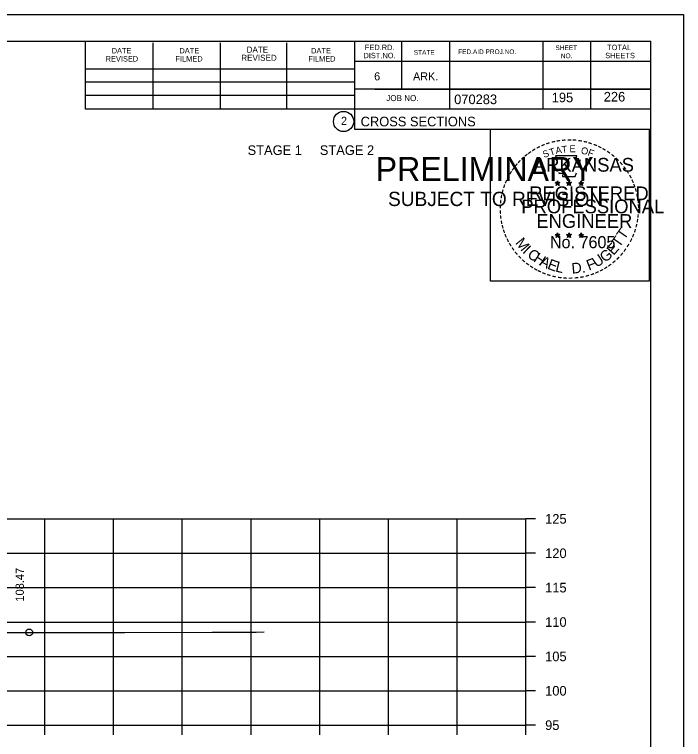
# Model space of a CAD drawing. Extents: x 1175611 to 1176402, y -433344 to -416213.
# Drawn here: x 1175846.5 to 1175943.9, y -422995.4 to -422890 of the extents above; entities that cross this region are included whole.
import ezdxf

# ---------------------------------------------------------------- set-up
doc = ezdxf.new("R2010")
doc.units = 0
for name, color, linetype in [('Default', 7, 'Continuous'), ('R_Axis', 7, 'Continuous'), ('R_Axis Annot', 7, 'Continuous'), ('R_Border', 7, 'Continuous'), ('R_Border Notes', 7, 'Continuous'), ('R_Border PE', 7, 'Continuous'), ('R_Border Prem', 7, 'Continuous'), ('R_Exist Surface', 7, 'Continuous'), ('R_Grid', 7, 'Continuous'), ('R_No Plot', 7, 'Continuous'), ('R_Xsect Elev', 7, 'Continuous')]:
    doc.layers.add(name, color=color, linetype=linetype)

msp = doc.modelspace()

# ---------------------------------------------------------------- linework, layer by layer
at = {"layer": 'R_Axis'}
for p, q in [((1175920.97, -422993.33), (1175920.97, -422963.33)), ((1175922.37, -422963.33), (1175920.97, -422963.33)), ((1175922.37, -422968.33), (1175920.97, -422968.33)), ((1175922.37, -422973.33), (1175920.97, -422973.33)), ((1175922.37, -422978.33), (1175920.97, -422978.33)), ((1175922.37, -422983.33), (1175920.97, -422983.33)), ((1175922.37, -422988.33), (1175920.97, -422988.33)), ((1175640.97, -422993.33), (1175920.97, -422993.33)), ((1175850.97, -422994.73), (1175850.97, -422993.33)), ((1175860.97, -422994.73), (1175860.97, -422993.33)), ((1175870.97, -422994.73), (1175870.97, -422993.33)), ((1175880.97, -422994.73), (1175880.97, -422993.33)), ((1175890.97, -422994.73), (1175890.97, -422993.33)), ((1175900.97, -422994.73), (1175900.97, -422993.33)), ((1175910.97, -422994.73), (1175910.97, -422993.33)), ((1175920.97, -422994.73), (1175920.97, -422993.33)), ((1175922.37, -422993.33), (1175920.97, -422993.33))]:
    msp.add_line(p, q, dxfattribs=at)
at = {"layer": 'R_Border'}
for p, q in [((1175622.97, -422893.87), (1175939.15, -422893.87)), ((1175856.89, -422903.75), (1175856.89, -422893.87)), ((1175866.75, -422903.75), (1175866.75, -422894.07)), ((1175876.51, -422903.75), (1175876.51, -422894.07)), ((1175886.19, -422903.75), (1175886.19, -422894.07)), ((1175896.05, -422893.87), (1175896.05, -422906.67)), ((1175902.89, -422893.87), (1175902.89, -422900.81)), ((1175909.83, -422893.87), (1175909.83, -422903.75)), ((1175923.41, -422893.87), (1175923.41, -422903.75)), ((1175930.35, -422893.87), (1175930.35, -422903.75)), ((1175939.15, -423099.33), (1175939.15, -422893.87)), ((1175939.15, -422896.81), (1175896.05, -422896.81)), ((1175939.15, -422896.79), (1175939.15, -422896.79)), ((1175856.89, -422897.89), (1175896.05, -422897.89)), ((1175856.89, -422899.75), (1175896.05, -422899.75)), ((1175939.15, -422900.81), (1175896.05, -422900.81)), ((1175899.01, -422900.81), (1175939.15, -422900.81)), ((1175856.89, -422903.75), (1175856.89, -422901.69)), ((1175856.89, -422901.69), (1175896.05, -422901.69)), ((1175939.15, -422903.75), (1175856.89, -422903.75)), ((1175896.05, -422906.67), (1175939.15, -422906.67))]:
    msp.add_line(p, q, dxfattribs=at)
msp.add_circle((1175894.44, -422905.53), 1.47, dxfattribs=at)
at = {"layer": 'R_Border PE'}
for p, q in [((1175925.23, -422914.42), (1175925.58, -422914.53)), ((1175925.23, -422914.42), (1175925.49, -422914.46)), ((1175925.23, -422914.42), (1175925.47, -422914.54)), ((1175925.37, -422914.83), (1175925.58, -422914.53)), ((1175925.37, -422914.83), (1175925.49, -422914.58)), ((1175925.37, -422914.83), (1175925.58, -422914.61)), ((1175925.58, -422914.17), (1175925.54, -422914.42)), ((1175925.58, -422914.53), (1175925.58, -422914.17)), ((1175925.58, -422914.17), (1175925.63, -422914.42)), ((1175925.93, -422914.42), (1175925.58, -422914.53)), ((1175925.8, -422914.83), (1175925.58, -422914.53)), ((1175925.8, -422914.83), (1175925.58, -422914.61)), ((1175925.93, -422914.42), (1175925.64, -422914.47)), ((1175925.8, -422914.83), (1175925.66, -422914.54)), ((1175925.93, -422914.42), (1175925.73, -422914.52)), ((1175926.9, -422914.42), (1175927.25, -422914.53)), ((1175926.9, -422914.42), (1175927.16, -422914.46)), ((1175926.9, -422914.42), (1175927.14, -422914.54)), ((1175927.04, -422914.83), (1175927.25, -422914.53)), ((1175927.04, -422914.83), (1175927.16, -422914.58)), ((1175927.04, -422914.83), (1175927.25, -422914.61)), ((1175927.25, -422914.17), (1175927.21, -422914.42)), ((1175927.25, -422914.53), (1175927.25, -422914.17)), ((1175927.25, -422914.17), (1175927.3, -422914.42)), ((1175927.6, -422914.42), (1175927.25, -422914.53)), ((1175927.47, -422914.83), (1175927.25, -422914.53)), ((1175927.47, -422914.83), (1175927.25, -422914.61)), ((1175927.6, -422914.42), (1175927.31, -422914.47)), ((1175927.47, -422914.83), (1175927.33, -422914.54)), ((1175927.6, -422914.42), (1175927.4, -422914.52)), ((1175928.67, -422914.43), (1175929.02, -422914.54)), ((1175928.67, -422914.43), (1175928.92, -422914.48)), ((1175928.67, -422914.43), (1175928.91, -422914.55)), ((1175928.8, -422914.84), (1175929.02, -422914.54)), ((1175928.8, -422914.84), (1175928.93, -422914.6)), ((1175928.8, -422914.84), (1175929.02, -422914.62)), ((1175929.02, -422914.18), (1175928.98, -422914.43)), ((1175929.02, -422914.54), (1175929.02, -422914.18)), ((1175929.02, -422914.18), (1175929.07, -422914.43)), ((1175929.36, -422914.43), (1175929.02, -422914.54)), ((1175929.23, -422914.84), (1175929.02, -422914.54)), ((1175929.23, -422914.84), (1175929.02, -422914.63)), ((1175929.36, -422914.43), (1175929.08, -422914.48)), ((1175929.23, -422914.84), (1175929.09, -422914.55)), ((1175929.36, -422914.43), (1175929.16, -422914.53)), ((1175925.23, -422921.99), (1175925.58, -422922.1)), ((1175925.23, -422921.99), (1175925.48, -422922.04)), ((1175925.23, -422921.99), (1175925.47, -422922.11)), ((1175925.58, -422921.74), (1175925.54, -422921.99)), ((1175925.58, -422922.1), (1175925.58, -422921.74)), ((1175925.58, -422921.74), (1175925.63, -422921.99)), ((1175925.93, -422921.99), (1175925.58, -422922.1)), ((1175925.93, -422921.99), (1175925.64, -422922.04)), ((1175925.93, -422921.99), (1175925.72, -422922.09)), ((1175926.9, -422921.99), (1175927.25, -422922.1)), ((1175926.9, -422921.99), (1175927.15, -422922.04)), ((1175926.9, -422921.99), (1175927.14, -422922.11)), ((1175927.25, -422921.74), (1175927.21, -422921.99)), ((1175927.25, -422922.1), (1175927.25, -422921.74)), ((1175927.25, -422921.74), (1175927.3, -422921.99)), ((1175927.6, -422921.99), (1175927.25, -422922.1)), ((1175927.6, -422921.99), (1175927.31, -422922.04)), ((1175927.6, -422921.99), (1175927.39, -422922.09)), ((1175928.67, -422922), (1175929.02, -422922.11)), ((1175928.67, -422922), (1175928.92, -422922.05)), ((1175928.67, -422922), (1175928.9, -422922.12)), ((1175929.02, -422921.75), (1175928.97, -422922)), ((1175929.02, -422922.11), (1175929.02, -422921.75)), ((1175929.02, -422921.75), (1175929.06, -422922)), ((1175929.36, -422922), (1175929.02, -422922.11)), ((1175929.36, -422922), (1175929.08, -422922.05)), ((1175929.36, -422922), (1175929.16, -422922.1)), ((1175925.36, -422922.4), (1175925.58, -422922.1)), ((1175925.36, -422922.4), (1175925.49, -422922.16)), ((1175925.36, -422922.4), (1175925.58, -422922.18)), ((1175925.79, -422922.4), (1175925.58, -422922.1)), ((1175925.79, -422922.4), (1175925.58, -422922.19)), ((1175925.79, -422922.4), (1175925.66, -422922.11)), ((1175927.03, -422922.4), (1175927.25, -422922.1)), ((1175927.03, -422922.4), (1175927.16, -422922.16)), ((1175927.03, -422922.4), (1175927.25, -422922.18)), ((1175927.46, -422922.4), (1175927.25, -422922.1)), ((1175927.46, -422922.4), (1175927.25, -422922.19)), ((1175927.46, -422922.4), (1175927.32, -422922.11)), ((1175928.8, -422922.41), (1175929.02, -422922.11)), ((1175928.8, -422922.41), (1175928.93, -422922.17)), ((1175928.8, -422922.41), (1175929.01, -422922.19)), ((1175929.23, -422922.41), (1175929.01, -422922.2)), ((1175929.23, -422922.41), (1175929.02, -422922.11)), ((1175929.23, -422922.41), (1175929.09, -422922.12))]:
    msp.add_line(p, q, dxfattribs=at)
for points in [[(1175925.28, -422910.54), (1175925.54, -422911.37)], [(1175928.79, -422911.46), (1175928.93, -422911.18), (1175928.24, -422911.2), (1175928.39, -422910.54), (1175925.28, -422910.54)], [(1175925.77, -422912.96), (1175925.77, -422913.05), (1175926.33, -422913.07), (1175926.28, -422913.54), (1175928.15, -422913.54), (1175928.35, -422913.01)], [(1175925.58, -422914.17), (1175925.8, -422914.83), (1175925.23, -422914.42), (1175925.93, -422914.42), (1175925.37, -422914.83), (1175925.58, -422914.17)], [(1175927.25, -422914.17), (1175927.47, -422914.83), (1175926.9, -422914.42), (1175927.6, -422914.42), (1175927.04, -422914.83), (1175927.25, -422914.17)], [(1175929.02, -422914.18), (1175929.23, -422914.84), (1175928.67, -422914.43), (1175929.36, -422914.43), (1175928.8, -422914.84), (1175929.02, -422914.18)], [(1175925.58, -422921.74), (1175925.79, -422922.4), (1175925.23, -422921.99), (1175925.93, -422921.99), (1175925.36, -422922.4), (1175925.58, -422921.74)], [(1175927.25, -422921.74), (1175927.46, -422922.4), (1175926.9, -422921.99), (1175927.6, -422921.99), (1175927.03, -422922.4), (1175927.25, -422921.74)], [(1175929.02, -422921.75), (1175929.23, -422922.41), (1175928.67, -422922), (1175929.36, -422922), (1175928.8, -422922.41), (1175929.02, -422921.75)]]:
    msp.add_lwpolyline(points, dxfattribs=at)
for centre, radius in [((1175925.58, -422914.53), 0.172), ((1175925.58, -422914.53), 0.145), ((1175925.58, -422914.53), 0.116), ((1175925.58, -422914.53), 0.0991), ((1175925.58, -422914.53), 0.0747), ((1175925.58, -422914.53), 0.0495), ((1175925.58, -422914.53), 0.0296), ((1175927.25, -422914.53), 0.172), ((1175927.25, -422914.53), 0.145), ((1175927.25, -422914.53), 0.116), ((1175927.25, -422914.53), 0.0991), ((1175927.25, -422914.53), 0.0747), ((1175927.25, -422914.53), 0.0495), ((1175927.25, -422914.53), 0.0296), ((1175929.02, -422914.54), 0.172), ((1175929.02, -422914.54), 0.145), ((1175929.02, -422914.54), 0.116), ((1175929.02, -422914.54), 0.0991), ((1175929.02, -422914.54), 0.0747), ((1175929.02, -422914.54), 0.0495), ((1175929.02, -422914.54), 0.0296), ((1175925.58, -422922.1), 0.172), ((1175925.58, -422922.1), 0.145), ((1175925.58, -422922.1), 0.116), ((1175925.58, -422922.1), 0.0991), ((1175927.25, -422922.1), 0.172), ((1175927.25, -422922.1), 0.145), ((1175927.25, -422922.1), 0.116), ((1175927.25, -422922.1), 0.0991), ((1175929.01, -422922.11), 0.172), ((1175929.01, -422922.11), 0.145), ((1175929.01, -422922.11), 0.116), ((1175929.01, -422922.11), 0.0991), ((1175925.58, -422922.1), 0.0747), ((1175925.58, -422922.1), 0.0495), ((1175925.58, -422922.1), 0.0296), ((1175927.25, -422922.1), 0.0747), ((1175927.25, -422922.1), 0.0495), ((1175927.25, -422922.1), 0.0296), ((1175929.01, -422922.11), 0.0747), ((1175929.01, -422922.11), 0.0495), ((1175929.01, -422922.11), 0.0296)]:
    msp.add_circle(centre, radius, dxfattribs=at)
at = {"layer": 'R_Exist Surface'}
msp.add_lwpolyline([(1175839.36, -422979.87), (1175862.58, -422979.83), (1175875.31, -422979.79), (1175881.73, -422979.8), (1175882.9, -422979.75)], dxfattribs=at)
at = {"layer": 'R_Grid'}
for p, q in [((1175640.97, -422963.33), (1175920.97, -422963.33)), ((1175850.97, -422993.33), (1175850.97, -422963.33)), ((1175860.97, -422993.33), (1175860.97, -422963.33)), ((1175870.97, -422993.33), (1175870.97, -422963.33)), ((1175880.97, -422993.33), (1175880.97, -422963.33)), ((1175890.97, -422993.33), (1175890.97, -422963.33)), ((1175900.97, -422993.33), (1175900.97, -422963.33)), ((1175910.97, -422993.33), (1175910.97, -422963.33)), ((1175920.97, -422993.33), (1175920.97, -422963.33)), ((1175640.97, -422968.33), (1175920.97, -422968.33)), ((1175640.97, -422973.33), (1175920.97, -422973.33)), ((1175640.97, -422978.33), (1175920.97, -422978.33)), ((1175640.97, -422983.33), (1175920.97, -422983.33)), ((1175640.97, -422988.33), (1175920.97, -422988.33)), ((1175640.97, -422993.33), (1175920.97, -422993.33))]:
    msp.add_line(p, q, dxfattribs=at)
at = {"layer": 'R_No Plot'}
msp.add_line((1175610.57, -422889.97), (1175943.91, -422889.97), dxfattribs=at)
for points in [[(1175610.57, -422889.97), (1175943.91, -422889.97), (1175943.91, -423103.31), (1175610.57, -423103.31)], [(1175915.82, -422906.63), (1175938.92, -422906.63), (1175938.92, -422928.78), (1175915.82, -422928.78)]]:
    msp.add_lwpolyline(points, close=True, dxfattribs=at)
msp.add_circle((1175848.69, -422979.85), 0.5, dxfattribs=at)

# ---------------------------------------------------------------- texts
at = {"layer": 'Default'}
msp.add_text('STAGE 1     STAGE 2', height=1.4, dxfattribs=at).set_placement((1175880.47, -422910.4))
at = {"layer": 'R_Axis Annot'}
for s, p in [('125', (1175923.77, -422964.03)), ('120', (1175923.77, -422969.03)), ('115', (1175923.77, -422974.03)), ('110', (1175923.77, -422979.03)), ('105', (1175923.77, -422984.03)), ('100', (1175923.77, -422989.03)), ('95', (1175923.77, -422994.03))]:
    msp.add_text(s, height=1.4, dxfattribs=at).set_placement(p)
at = {"layer": 'R_Border'}
for s, height, p in [('FED.RD.', 0.782, (1175897.53, -422895.15)), ('SHEET', 0.684, (1175925.27, -422895.15)), ('TOTAL', 0.782, (1175932.79, -422895.15)), ('DATE', 0.782, (1175860.69, -422895.63)), ('DATE', 0.782, (1175870.55, -422895.63)), ('DATE', 0.879, (1175880.33, -422895.53)), ('DATE', 0.782, (1175889.71, -422895.63)), ('DIST.NO.', 0.782, (1175897.33, -422896.33)), ('STATE', 0.684, (1175904.65, -422895.83)), ('FED.AID PROJ.NO.', 0.684, (1175911.11, -422895.73)), ('NO.', 0.684, (1175926.05, -422896.33)), ('SHEETS', 0.782, (1175932.51, -422896.33)), ('REVISED', 0.782, (1175859.81, -422896.81)), ('FILMED', 0.782, (1175869.97, -422896.81)), ('REVISED', 0.879, (1175879.55, -422896.71)), ('FILMED', 0.782, (1175889.31, -422896.81)), ('6', 1.17, (1175898.89, -422899.55)), ('ARK.', 1.172, (1175904.55, -422899.55)), ('JOB NO.', 0.879, (1175900.65, -422902.57)), ('070283', 1.4, (1175910.53, -422903.01)), ('2', 1.17, (1175894.06, -422906.02)), ('CROSS SECTIONS', 1.4, (1175896.92, -422906.24))]:
    msp.add_text(s, height=height, rotation=360, dxfattribs=at).set_placement(p)
at = {"layer": 'R_Border Notes'}
for s, p in [('195', (1175924.73, -422902.74)), ('226', (1175932.3, -422902.63))]:
    msp.add_text(s, height=1.4, dxfattribs=at).set_placement(p)
at = {"layer": 'R_Border PE'}
for s, height, rotation, p in [('-', 1.6, 10.2193, (1175925.45, -422909.01)), ('-', 1.6, 5.8968, (1175926.18, -422908.9)), ('-', 1.6, 0.1862, (1175926.95, -422908.83)), ('-', 1.6, 357.743, (1175927.67, -422908.84)), ('-', 1.6, 352.1617, (1175928.42, -422908.9)), ('-', 1.6, 28.7918, (1175922.76, -422910)), ('-', 1.6, 24.3072, (1175923.39, -422909.68)), ('-', 1.6, 19.1761, (1175924.02, -422909.41)), ('T', 1, 16.4036, (1175924.54, -422910.53)), ('-', 1.6, 13.6301, (1175924.77, -422909.17)), ('A', 1, 11.2132, (1175925.37, -422910.28)), ('T', 1, 6.0228, (1175926.22, -422910.12)), ('E', 1, 0.8323, (1175927.32, -422910.01)), ('O', 1, 350.4515, (1175928.93, -422910.22)), ('-', 1.6, 347.2049, (1175929.14, -422909.01)), ('-', 1.6, 342.3362, (1175929.77, -422909.17)), ('-', 1.6, 337.8551, (1175930.51, -422909.39)), ('-', 1.6, 334.1211, (1175931.14, -422909.66)), ('-', 1.6, 38.9507, (1175921.1, -422911.14)), ('-', 1.6, 36.2317, (1175921.58, -422910.77)), ('-', 1.6, 34.0636, (1175922.16, -422910.37)), ('S', 1, 21.594, (1175923.63, -422910.86)), ('F', 1, 340.0707, (1175929.88, -422910.44)), ('-', 1.6, 329.6409, (1175931.72, -422909.94)), ('-', 1.6, 325.8627, (1175932.36, -422910.31)), ('-', 1.6, 320.5297, (1175932.97, -422910.73)), ('-', 1.6, 48.423, (1175920.22, -422912.04)), ('-', 1.6, 42.9622, (1175920.67, -422911.56)), ('ARKANSAS', 2, 360, (1175922.13, -422912.83)), ('-', 1.6, 315.5786, (1175933.57, -422911.22)), ('-', 1.6, 309.8797, (1175934.14, -422911.77)), ('-', 1.6, 54.2325, (1175919.41, -422913.09)), ('-', 1.6, 50.6142, (1175919.82, -422912.52)), ('-', 1.6, 306.6522, (1175934.66, -422912.37)), ('-', 1.6, 62.8713, (1175918.77, -422914.23)), ('-', 1.6, 58.0706, (1175919.08, -422913.62)), ('-', 1.4, 303.6753, (1175935.15, -422912.94)), ('-', 1.6, 299.6684, (1175935.47, -422913.55)), ('-', 1.6, 67.7743, (1175918.51, -422914.84)), ('DWB', 0.01, 360, (1175925.57, -422914.54)), ('DWB', 0.01, 360, (1175927.24, -422914.54)), ('DWB', 0.01, 360, (1175929, -422914.55)), ('-', 1.6, 294.6628, (1175935.79, -422914.16)), ('-', 1.6, 290.5728, (1175936.05, -422914.74)), ('-', 1.6, 75.461, (1175918.09, -422916.19)), ('-', 1.6, 72.3945, (1175918.29, -422915.47)), ('REGISTERED', 2, 360, (1175921.45, -422916.98)), ('-', 1.6, 285.1233, (1175936.28, -422915.32)), ('-', 1.6, 81.2013, (1175917.96, -422916.9)), ('-', 1.6, 280.5493, (1175936.48, -422916.06)), ('-', 1.6, 89.0622, (1175917.86, -422918.29)), ('-', 1.6, 85.1863, (1175917.89, -422917.59)), ('PROFESSIONAL', 2, 360, (1175920.3, -422918.88)), ('-', 1.6, 276.5962, (1175936.65, -422916.83)), ('-', 1.6, 274.3301, (1175936.71, -422917.55)), ('-', 1.6, 94.1959, (1175917.9, -422919.02)), ('-', 1.6, 269.9407, (1175936.74, -422918.18)), ('-', 1.6, 98.9479, (1175917.97, -422919.68)), ('ENGINEER', 2, 360, (1175922.49, -422921.01)), ('-', 1.6, 260.9953, (1175936.65, -422919.5)), ('-', 1.6, 263.5172, (1175936.72, -422918.85)), ('-', 1.6, 101.7149, (1175918.1, -422920.42)), ('-', 1.6, 105.4578, (1175918.27, -422921.01)), ('T', 1.54, 55.055, (1175935.3, -422922.84)), ('-', 1.6, 255.7626, (1175936.54, -422920.18)), ('-', 1.6, 109.0874, (1175918.48, -422921.64)), ('-', 1.6, 114.0643, (1175918.73, -422922.24)), ('-', 1.6, 247.8887, (1175936.14, -422921.57)), ('-', 1.6, 252.8681, (1175936.36, -422920.9)), ('-', 1.6, 115.7289, (1175919.04, -422922.86)), ('M', 1.54, 308.9175, (1175919.35, -422923.21)), ('No. 7605', 1.757, 360, (1175924.46, -422923.96)), ('DWB', 0.01, 360, (1175925.56, -422922.11)), ('DWB', 0.01, 360, (1175927.23, -422922.11)), ('DWB', 0.01, 360, (1175929, -422922.12)), ('T', 1.54, 55.055, (1175934.57, -422923.96)), ('-', 1.6, 244.6197, (1175935.87, -422922.2)), ('-', 1.6, 120.4471, (1175919.4, -422923.44)), ('-', 1.6, 125.8934, (1175919.8, -422924)), ('I', 1.54, 316.4636, (1175920.39, -422924.53)), ('E', 1.54, 48.7313, (1175933.72, -422925.09)), ('-', 1.6, 233.8452, (1175935.08, -422923.6)), ('-', 1.6, 239.0712, (1175935.48, -422922.95)), ('-', 1.6, 130.7181, (1175920.26, -422924.56)), ('-', 1.6, 134.2238, (1175920.78, -422925.1)), ('C', 1.54, 324.0197, (1175921.06, -422925.16)), ('H', 1.54, 327.5342, (1175921.97, -422925.81)), ('U', 1.54, 34.4052, (1175931.27, -422926.84)), ('G', 1.54, 38.2173, (1175932.47, -422926.11)), ('-', 1.6, 225.7653, (1175934.17, -422924.73)), ('-', 1.6, 231.2538, (1175934.65, -422924.17)), ('-', 1.6, 138.9338, (1175921.3, -422925.57)), ('-', 1.6, 144.6463, (1175921.86, -422925.97)), ('A', 1.54, 332.5513, (1175922.83, -422926.35)), ('E', 1.54, 339.2068, (1175923.99, -422926.91)), ('L', 1.54, 346.2929, (1175925.18, -422927.33)), ('D.', 1.54, 5.2602, (1175927.68, -422927.67)), ('F', 1.54, 20.8202, (1175930.13, -422927.23)), ('-', 1.6, 215.7363, (1175933.1, -422925.72)), ('-', 1.6, 221.0851, (1175933.65, -422925.24)), ('-', 1.6, 148.0898, (1175922.42, -422926.34)), ('-', 1.6, 151.5704, (1175923, -422926.67)), ('-', 1.6, 154.6002, (1175923.52, -422926.91)), ('-', 1.6, 204.2516, (1175931.38, -422926.77)), ('-', 1.6, 207.3568, (1175932.01, -422926.45)), ('-', 1.6, 212.2491, (1175932.56, -422926.1)), ('-', 1.6, 158.5612, (1175924.15, -422927.17)), ('-', 1.6, 162.7983, (1175924.83, -422927.38)), ('-', 1.6, 167.5555, (1175925.55, -422927.55)), ('-', 1.6, 173.1155, (1175926.32, -422927.66)), ('-', 1.6, 176.5183, (1175927.07, -422927.71)), ('-', 1.6, 181.5918, (1175927.81, -422927.69)), ('-', 1.6, 185.8167, (1175928.62, -422927.61)), ('-', 1.6, 191.2858, (1175929.36, -422927.48)), ('-', 1.6, 195.4743, (1175930.09, -422927.28)), ('-', 1.6, 200.7184, (1175930.76, -422927.04))]:
    msp.add_text(s, height=height, rotation=rotation, dxfattribs=at).set_placement(p)
at = {"layer": 'R_Border Prem'}
for s, height, p in [('PRELIMINARY', 3.5, (1175899.1, -422914.2)), ('DWB', 0.01, (1175899.85, -422912.35)), ('SUBJECT TO REVISION', 2.0751, (1175900.91, -422917.83))]:
    msp.add_text(s, height=height, rotation=360, dxfattribs=at).set_placement(p)
at = {"layer": 'R_Xsect Elev'}
msp.add_text('108.47', height=1.2, rotation=90, dxfattribs=at).set_placement((1175847.91, -422975.36))

doc.saveas('drawing.dxf')
